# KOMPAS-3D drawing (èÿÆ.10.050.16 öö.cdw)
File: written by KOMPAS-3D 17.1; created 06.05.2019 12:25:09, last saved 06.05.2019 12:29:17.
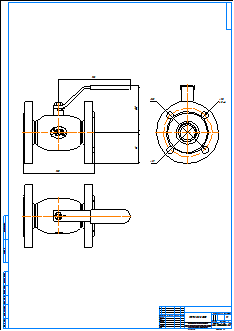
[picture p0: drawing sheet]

Sheet 1: A1, portrait

Title block, sheet 1: name: КШТ.10.050.16 ФФ; material: Внимание! Данный продукт является объектом авторского права ООО «Торговый Дом АДЛ». / Запрещается изменение, копирование, распространение / (в том числе путем копирования на другие сайты и ресурсы в Интернете) / или любое иное использование информации и объектов без предварительного / согласия правообладателя (ООО «Торговый Дом АДЛ»).; sheets: 1; organisation: ООО "Торговый дом АДЛ"; sheet format: A1; stored path: C:\Users\tra\Desktop\2д чертежи\Шаровые краны БИВАЛ\КШ_Бивал_серия_10\KOMPAS 2D\КШТ.10.050.16 ФФ.cdw

Views: Вид 1, Проекционный вид 2, Проекционный вид 3
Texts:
  user
Dimensions and other numbers on the sheet: 180; 183; 121; 80; 125; 39; 18; 4 Отв.; 1:1; 1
